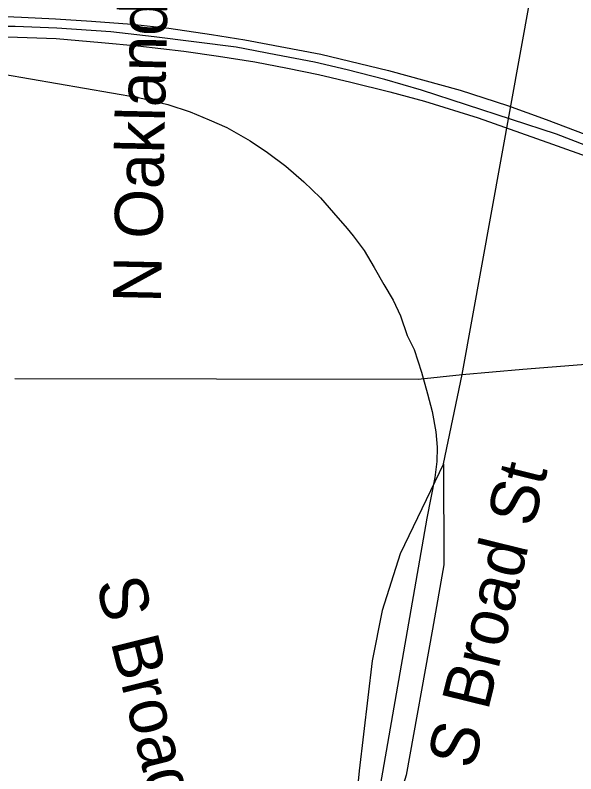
# Model space of a CAD drawing. Extents: x 1268485 to 1426702, y 514839 to 616766.
# Drawn here: x 1349305 to 1350072, y 557544 to 558583 of the extents above; entities that cross this region are included whole.
import ezdxf

# ---------------------------------------------------------------- set-up
doc = ezdxf.new("R2010")
doc.units = 0
for name, color, linetype in [('Old_Level_10', 7, 'Continuous'), ('Old_Level_31', 7, 'Continuous'), ('Old_Level_35', 7, 'Continuous'), ('Old_Level_44', 7, 'Continuous'), ('Old_Level_50', 7, 'Continuous')]:
    doc.layers.add(name, color=color, linetype=linetype)

msp = doc.modelspace()

# ---------------------------------------------------------------- linework, layer by layer
at = {"layer": 'Old_Level_31'}
msp.add_line((1349973.43, 558457.131), (1349973.43, 558457.131), dxfattribs=at)
at = {"layer": 'Old_Level_35'}
for p, q in [((1349916.715, 558090.82), (1350033.287, 558734.889)), ((1349891.289, 557968.762), (1349916.715, 558090.82))]:
    msp.add_line(p, q, dxfattribs=at)
for points in [[(1349916.715, 558090.82), (1349999.966, 558098.253), (1350131.917, 558108.71), (1350163.598, 558109.582), (1350212.4, 558112.145), (1350260.587, 558112.556), (1350302.521, 558112.556), (1350356.347, 558110.453), (1350487.58, 558096.51), (1350648.648, 558065.752), (1351018.255, 557966.609), (1351198.085, 557932.827), (1351252.834, 557924.318), (1351260.831, 557921.755), (1351267.906, 557917.807), (1351274.16, 557913.398)], [(1349304.84, 558085.386), (1349856.84, 558084.617), (1349916.715, 558090.82)], [(1349891.289, 557968.762), (1349831.926, 557845.116), (1349807.627, 557767.709), (1349793.889, 557698.863), (1349775.742, 557548.252), (1349771.538, 557501.551)], [(1349891.289, 557968.762), (1349891.904, 557830.199), (1349876.422, 557742.18), (1349840.128, 557541.998), (1349826.709, 557498.053)]]:
    msp.add_lwpolyline(points, dxfattribs=at)
at = {"layer": 'Old_Level_44'}
for points in [[(1349027.302, 558572.641), (1349101.325, 558577.819), (1349152.588, 558580.894), (1349187.345, 558581.458), (1349220.051, 558580.894), (1349271.211, 558581.92), (1349313.759, 558580.382), (1349360.409, 558577.819), (1349409.519, 558574.691), (1349464.985, 558570.539), (1349515.736, 558565.361), (1349573.765, 558556.544), (1349619.39, 558549.316), (1349723.453, 558529.631), (1349816.24, 558507.332), (1349914.152, 558480.367), (1349978.846, 558459.144), (1350031.749, 558440.024), (1350097.981, 558415.11), (1350154.986, 558391.836), (1350222.858, 558364.359), (1350531.666, 558235.382)], [(1350387.617, 558280.954), (1350173.645, 558369.024), (1350132.225, 558386.608), (1350045.795, 558419.826), (1349861.248, 558480.367), (1349811.011, 558494.875), (1349759.748, 558508.357), (1349714.636, 558518.764), (1349661.835, 558528.555), (1349607.496, 558538.961), (1349495.538, 558553.418), (1349435.97, 558560.184), (1349362.357, 558565.361), (1349305.352, 558567.464), (1349273.877, 558567.464), (1349183.756, 558567.464), (1349101.325, 558563.823), (1348987.419, 558555.006), (1348794.67, 558535.629)], [(1348935.848, 558535.629), (1349032.325, 558544.651), (1349092.508, 558549.316), (1349152.588, 558552.956), (1349210.618, 558552.956), (1349247.835, 558554.494), (1349308.531, 558552.956), (1349361.331, 558550.854), (1349423.462, 558545.676), (1349473.29, 558541.012), (1349536.036, 558533.733), (1349583.608, 558527.017), (1349633.333, 558519.276), (1349677.829, 558510.459), (1349720.378, 558501.642), (1349764.361, 558491.235), (1349817.777, 558477.804), (1349865.349, 558465.398), (1349938.963, 558442.587), (1350040.464, 558406.293), (1350092.855, 558387.684)], [(1349251.731, 558508.459), (1349474.008, 558470.269), (1349514.095, 558460.682), (1349544.853, 558450.635), (1349570.485, 558439.562), (1349595.091, 558429.002), (1349626.771, 558410.855), (1349650.352, 558394.81), (1349675.676, 558376.201), (1349700.283, 558354.568), (1349722.838, 558332.935), (1349740.883, 558312.379), (1349759.543, 558290.746), (1349767.642, 558280.698), (1349782.611, 558260.551), (1349796.247, 558237.432), (1349809.883, 558214.312), (1349822.391, 558192.679), (1349832.541, 558171.046), (1349841.461, 558144.441), (1349850.996, 558125.32), (1349861.146, 558094.101), (1349869.656, 558064.419), (1349875.602, 558040.326), (1349880.728, 558012.183), (1349882.779, 557991.575), (1349882.779, 557991.062), (1349882.266, 557971.941), (1349879.703, 557949.795), (1349868.63, 557894.021), (1349799.733, 557499.296)]]:
    msp.add_lwpolyline(points, dxfattribs=at)
at = {"layer": 'Old_Level_50'}
msp.add_line((1349973.429, 558457.131), (1349973.429, 558457.131), dxfattribs=at)

# ---------------------------------------------------------------- texts
at = {"layer": 'Old_Level_10'}
for s, height, rotation, p in [('N Oakland St', 65.61666, 88.741714, (1349504.591, 558188.467)), ('S Broad St', 65.6167, 76.134275, (1349932.189, 557548.587)), ('S Broad St', 65.6167, 284.033064, (1349415.525, 557805.506))]:
    msp.add_text(s, height=height, rotation=rotation, dxfattribs=at).set_placement(p)

doc.saveas('drawing.dxf')
